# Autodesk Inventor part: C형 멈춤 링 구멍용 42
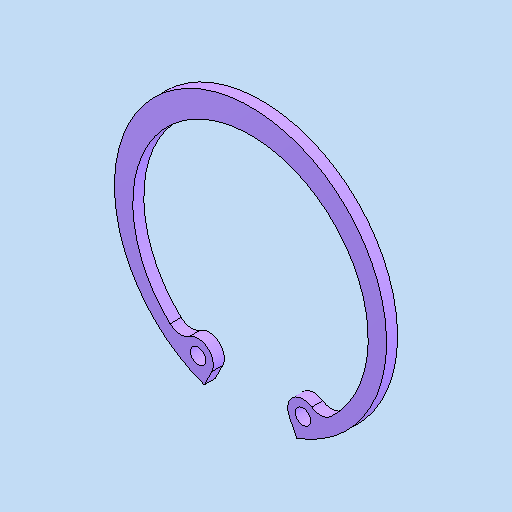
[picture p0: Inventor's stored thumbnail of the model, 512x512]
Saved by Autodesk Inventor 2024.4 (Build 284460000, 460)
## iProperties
Created: 2025-11
Part Number: C형 멈춤 링 구멍용 42
Material: 강철, 연강
Description: 리테이닝 링(C형)
Document SubType Name: Modeling
Designer: home
Density: 7.85 g/cm^3
Appearance: 기본값
Author: jhkim
Sending System: Autodesk Inventor 2026
Preprocessor: ST-DEVELOPER v20.1
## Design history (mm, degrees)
feature "Solid1"
node "솔리드1"
